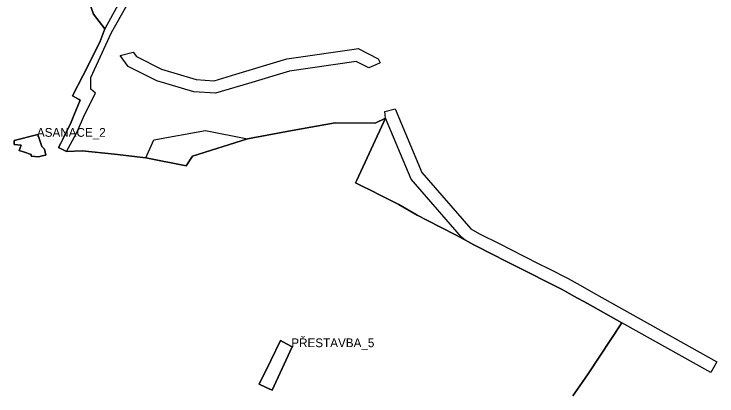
# Model space of a CAD drawing. Extents: x -521621 to -516761, y -1190184 to -1184927.
# Drawn here: x -518688 to -518124, y -1187044 to -1186738 of the extents above; entities that cross this region are included whole.
import ezdxf

# ---------------------------------------------------------------- set-up
doc = ezdxf.new("R2010")
doc.units = 0
for name, color, linetype in [('asanace_n', 7, 'Continuous'), ('hran_SZUO_P-s', 7, 'Continuous'), ('HZU_P_s', 7, 'Continuous'), ('Implicitní', 7, 'Continuous'), ('prestavba_n', 7, 'Continuous'), ('zastavitelne plochy', 7, 'Continuous')]:
    doc.layers.add(name, color=color, linetype=linetype)

msp = doc.modelspace()

# ---------------------------------------------------------------- linework, layer by layer
at = {"layer": 'asanace_n'}
msp.add_lwpolyline([(-518687.61, -1186839.39), (-518687.46, -1186842.75), (-518681.84, -1186843.35), (-518683.49, -1186847.57), (-518680.05, -1186848.65), (-518673.76, -1186850.63), (-518673.76, -1186852.08), (-518668.04, -1186852.69), (-518665.01, -1186851.93), (-518662.02, -1186851.18), (-518663.22, -1186846.36), (-518665.28, -1186844.36), (-518666.92, -1186839.49), (-518668.54, -1186834.67), (-518687.61, -1186839.39)], dxfattribs=at)
at = {"layer": 'hran_SZUO_P-s'}
for points in [[(-518623.97, -1186738.16), (-518631.26, -1186717.27)], [(-518614.96, -1186749.91), (-518623.97, -1186738.16)], [(-518618.97, -1186760.67), (-518614.96, -1186749.91)], [(-518632.48, -1186787.66), (-518618.97, -1186760.67)], [(-518640.78, -1186803.61), (-518632.48, -1186787.66)], [(-518636.04, -1186806.34), (-518638.41, -1186804.98), (-518640.78, -1186803.61)], [(-518639.56, -1186819.46), (-518634.57, -1186807.18)], [(-518634.57, -1186807.18), (-518635.31, -1186806.76), (-518636.04, -1186806.34)], [(-518641.7, -1186824.74), (-518639.56, -1186819.46)], [(-518412.82, -1186871.29), (-518389.67, -1186821.59)], [(-518389.67, -1186821.59), (-518398.17, -1186825.64)], [(-518644.86, -1186830.91), (-518641.7, -1186824.74)], [(-518430.15, -1186825.45), (-518464.52, -1186831.6)], [(-518398.17, -1186825.64), (-518430.15, -1186825.45)], [(-518648.33, -1186837.98), (-518646.6, -1186834.45), (-518644.86, -1186830.91)], [(-518464.52, -1186831.6), (-518500.52, -1186838.13)], [(-518651.88, -1186845.21), (-518650.11, -1186841.59), (-518648.33, -1186837.98)], [(-518500.52, -1186838.13), (-518544.49, -1186852.05)], [(-518645.57, -1186848.44), (-518651.88, -1186845.21)], [(-518632.89, -1186847.81), (-518645.57, -1186848.44)], [(-518607.21, -1186850.56), (-518632.89, -1186847.81)], [(-518582.03, -1186853.35), (-518607.21, -1186850.56)], [(-518544.49, -1186852.05), (-518549.49, -1186859.73)], [(-518549.49, -1186859.73), (-518582.03, -1186853.35)], [(-518413.79, -1186873.35), (-518412.82, -1186871.29)], [(-518408.98, -1186875.78), (-518413.79, -1186873.35)], [(-518401.24, -1186879.69), (-518408.98, -1186875.78)], [(-518394.12, -1186883.3), (-518401.24, -1186879.69)], [(-518386.57, -1186887.11), (-518394.12, -1186883.3)], [(-518379.12, -1186890.88), (-518386.57, -1186887.11)], [(-518364.49, -1186899.38), (-518379.12, -1186890.88)], [(-518356.21, -1186903.58), (-518364.49, -1186899.38)], [(-518333.61, -1186915.03), (-518356.21, -1186903.58)], [(-518326.21, -1186919.18), (-518333.61, -1186915.03)], [(-518319.05, -1186923.2), (-518326.21, -1186919.18)], [(-518302.73, -1186931.42), (-518319.05, -1186923.2)], [(-518294.42, -1186935.61), (-518302.73, -1186931.42)], [(-518271.38, -1186947.21), (-518294.42, -1186935.61)], [(-518263.64, -1186951.11), (-518271.38, -1186947.21)], [(-518248.17, -1186958.9), (-518263.64, -1186951.11)], [(-518238.68, -1186964.21), (-518248.17, -1186958.9)], [(-518227.87, -1186970.26), (-518238.68, -1186964.21)], [(-518200.37, -1186985.64), (-518227.87, -1186970.26)], [(-518227.43, -1187026.44), (-518200.37, -1186985.64)], [(-518232, -1187033.55), (-518227.43, -1187026.44)], [(-518235.74, -1187038.92), (-518232, -1187033.55)], [(-518239.49, -1187044.29), (-518235.74, -1187038.92)]]:
    msp.add_lwpolyline(points, dxfattribs=at)
at = {"layer": 'HZU_P_s'}
for p, q in [((-518632.48, -1186787.66), (-518640.78, -1186803.61)), ((-518634.57, -1186807.18), (-518639.56, -1186819.46)), ((-518639.56, -1186819.46), (-518641.7, -1186824.74)), ((-518389.67, -1186821.59), (-518412.82, -1186871.29)), ((-518398.17, -1186825.64), (-518389.67, -1186821.59)), ((-518464.52, -1186831.6), (-518430.15, -1186825.45)), ((-518430.15, -1186825.45), (-518398.17, -1186825.64)), ((-518500.52, -1186838.13), (-518464.52, -1186831.6)), ((-518544.49, -1186852.05), (-518500.52, -1186838.13)), ((-518651.88, -1186845.21), (-518645.57, -1186848.44)), ((-518645.57, -1186848.44), (-518632.89, -1186847.81)), ((-518632.89, -1186847.81), (-518607.21, -1186850.56)), ((-518607.21, -1186850.56), (-518582.03, -1186853.35)), ((-518549.49, -1186859.73), (-518544.49, -1186852.05)), ((-518582.03, -1186853.35), (-518549.49, -1186859.73)), ((-518412.82, -1186871.29), (-518413.79, -1186873.35)), ((-518232, -1187033.55), (-518235.74, -1187038.92)), ((-518235.74, -1187038.92), (-518239.49, -1187044.29))]:
    msp.add_line(p, q, dxfattribs=at)
for points in [[(-518631.26, -1186717.27), (-518623.97, -1186738.16)], [(-518623.97, -1186738.16), (-518614.96, -1186749.91)], [(-518614.96, -1186749.91), (-518618.97, -1186760.67)], [(-518618.97, -1186760.67), (-518632.48, -1186787.66)], [(-518640.78, -1186803.61), (-518638.41, -1186804.98), (-518636.04, -1186806.34)], [(-518636.04, -1186806.34), (-518635.31, -1186806.76), (-518634.57, -1186807.18)], [(-518641.7, -1186824.74), (-518644.86, -1186830.91)], [(-518644.86, -1186830.91), (-518646.6, -1186834.45), (-518648.33, -1186837.98)], [(-518648.33, -1186837.98), (-518650.11, -1186841.59), (-518651.88, -1186845.21)], [(-518413.79, -1186873.35), (-518408.98, -1186875.78)], [(-518408.98, -1186875.78), (-518401.24, -1186879.69), (-518394.12, -1186883.3)], [(-518394.12, -1186883.3), (-518386.57, -1186887.11), (-518379.12, -1186890.88)], [(-518379.12, -1186890.88), (-518364.49, -1186899.38)], [(-518364.49, -1186899.38), (-518356.21, -1186903.58)], [(-518356.21, -1186903.58), (-518333.61, -1186915.03)], [(-518333.61, -1186915.03), (-518326.21, -1186919.18)], [(-518326.21, -1186919.18), (-518319.05, -1186923.2)], [(-518319.05, -1186923.2), (-518302.73, -1186931.42), (-518294.42, -1186935.61)], [(-518294.42, -1186935.61), (-518271.38, -1186947.21)], [(-518271.38, -1186947.21), (-518263.64, -1186951.11), (-518248.17, -1186958.9)], [(-518248.17, -1186958.9), (-518238.68, -1186964.21)], [(-518238.68, -1186964.21), (-518227.87, -1186970.26)], [(-518227.87, -1186970.26), (-518200.37, -1186985.64)], [(-518200.37, -1186985.64), (-518227.43, -1187026.44)], [(-518227.43, -1187026.44), (-518232, -1187033.55)]]:
    msp.add_lwpolyline(points, dxfattribs=at)
at = {"layer": 'Implicitní'}
for p, q in [((-518390.39, -1186816.31), (-518381.92, -1186814.18)), ((-518389.67, -1186821.59), (-518390.39, -1186816.31)), ((-518381.92, -1186814.18), (-518360.74, -1186865.22)), ((-518369.34, -1186870.58), (-518389.67, -1186821.59)), ((-518534.01, -1186831.46), (-518500.52, -1186838.13)), ((-518500.52, -1186838.13), (-518544.49, -1186852.05)), ((-518544.49, -1186852.05), (-518549.49, -1186859.73)), ((-518549.49, -1186859.73), (-518582.03, -1186853.35)), ((-518360.74, -1186865.22), (-518321.32, -1186910.46)), ((-518328.85, -1186917.03), (-518369.34, -1186870.58)), ((-518321.32, -1186910.46), (-518314.35, -1186914.37)), ((-518314.35, -1186914.37), (-518298.23, -1186922.49)), ((-518326.21, -1186919.18), (-518328.85, -1186917.03)), ((-518319.05, -1186923.2), (-518326.21, -1186919.18)), ((-518302.73, -1186931.42), (-518319.05, -1186923.2)), ((-518298.23, -1186922.49), (-518289.92, -1186926.67)), ((-518294.42, -1186935.61), (-518302.73, -1186931.42)), ((-518289.92, -1186926.67), (-518266.88, -1186938.28)), ((-518271.38, -1186947.21), (-518294.42, -1186935.61)), ((-518266.88, -1186938.28), (-518259.14, -1186942.18)), ((-518259.14, -1186942.18), (-518243.48, -1186950.07)), ((-518263.64, -1186951.11), (-518271.38, -1186947.21)), ((-518248.17, -1186958.9), (-518263.64, -1186951.11)), ((-518243.48, -1186950.07), (-518233.8, -1186955.48)), ((-518238.68, -1186964.21), (-518248.17, -1186958.9)), ((-518233.8, -1186955.48), (-518222.99, -1186961.53)), ((-518227.87, -1186970.26), (-518238.68, -1186964.21)), ((-518222.99, -1186961.53), (-518124.07, -1187016.86)), ((-518200.37, -1186985.64), (-518227.87, -1186970.26)), ((-518128.95, -1187025.59), (-518200.37, -1186985.64)), ((-518481.7, -1187015.82), (-518473.89, -1186999.89)), ((-518473.89, -1186999.89), (-518469.1, -1187002.53)), ((-518469.1, -1187002.53), (-518464.51, -1187005.06)), ((-518464.51, -1187005.06), (-518480.71, -1187039.72)), ((-518491.05, -1187034.9), (-518481.7, -1187015.82)), ((-518126.55, -1187021.3), (-518128.95, -1187025.59)), ((-518124.07, -1187016.86), (-518126.55, -1187021.3)), ((-518485.93, -1187037.37), (-518491.05, -1187034.9)), ((-518480.71, -1187039.72), (-518485.93, -1187037.37))]:
    msp.add_line(p, q, dxfattribs=at)
for points in [[(-518509.83, -1186786.39), (-518468.84, -1186774.15), (-518414.86, -1186766.32), (-518411.76, -1186765.87), (-518395.6, -1186773.95), (-518394.12, -1186777.23), (-518397.68, -1186778.82), (-518403.25, -1186781.31), (-518413.43, -1186776.22), (-518466.68, -1186783.94), (-518499.74, -1186793.81)], [(-518573.01, -1186791.65), (-518596.15, -1186780.08), (-518602.48, -1186771.28), (-518592.03, -1186768.69), (-518589.47, -1186772.24), (-518569.32, -1186782.32)], [(-518569.32, -1186782.32), (-518541.73, -1186790.55), (-518527.2, -1186791.58), (-518509.83, -1186786.39)], [(-518499.74, -1186793.81), (-518526.09, -1186801.68), (-518543.53, -1186800.45), (-518573.01, -1186791.65)], [(-518582.03, -1186853.35), (-518575.51, -1186839.1), (-518534.01, -1186831.46)]]:
    msp.add_lwpolyline(points, dxfattribs=at)
msp.add_lwpolyline([(-518687.61, -1186839.39), (-518668.54, -1186834.67), (-518666.92, -1186839.49), (-518665.28, -1186844.36), (-518663.22, -1186846.36), (-518662.02, -1186851.18), (-518665.01, -1186851.93), (-518668.04, -1186852.69), (-518673.76, -1186852.08), (-518673.76, -1186850.63), (-518680.05, -1186848.65), (-518683.49, -1186847.57), (-518681.84, -1186843.35), (-518687.46, -1186842.75)], close=True, dxfattribs=at)
at = {"layer": 'prestavba_n'}
msp.add_lwpolyline([(-518491.05, -1187034.9), (-518485.93, -1187037.37), (-518480.71, -1187039.72), (-518464.51, -1187005.06), (-518469.1, -1187002.53), (-518473.89, -1186999.89), (-518481.7, -1187015.82), (-518491.05, -1187034.9)], dxfattribs=at)
at = {"layer": 'zastavitelne plochy'}
msp.add_lwpolyline([(-518640.78, -1186803.61), (-518636.04, -1186806.34), (-518634.57, -1186807.18), (-518639.56, -1186819.46), (-518641.7, -1186824.74), (-518644.86, -1186830.91), (-518648.33, -1186837.98), (-518651.88, -1186845.21), (-518645.57, -1186848.44), (-518640.87, -1186839.62), (-518637.14, -1186832.63), (-518631.11, -1186818.96), (-518622.31, -1186801.58), (-518626.04, -1186798.45), (-518626.13, -1186788.95), (-518609.53, -1186753.03), (-518585.35, -1186710.11), (-518587.46, -1186700.16), (-518614.96, -1186749.91), (-518618.97, -1186760.67), (-518632.48, -1186787.66), (-518640.78, -1186803.61)], dxfattribs=at)

# ---------------------------------------------------------------- texts
at = {"layer": 'asanace_n'}
msp.add_text('ASANACE_2', height=7, dxfattribs=at).set_placement((-518669.28, -1186836.54))
at = {"layer": 'prestavba_n'}
msp.add_text('PŘESTAVBA_5', height=7, dxfattribs=at).set_placement((-518465.33, -1187005.19))

doc.saveas('drawing.dxf')
